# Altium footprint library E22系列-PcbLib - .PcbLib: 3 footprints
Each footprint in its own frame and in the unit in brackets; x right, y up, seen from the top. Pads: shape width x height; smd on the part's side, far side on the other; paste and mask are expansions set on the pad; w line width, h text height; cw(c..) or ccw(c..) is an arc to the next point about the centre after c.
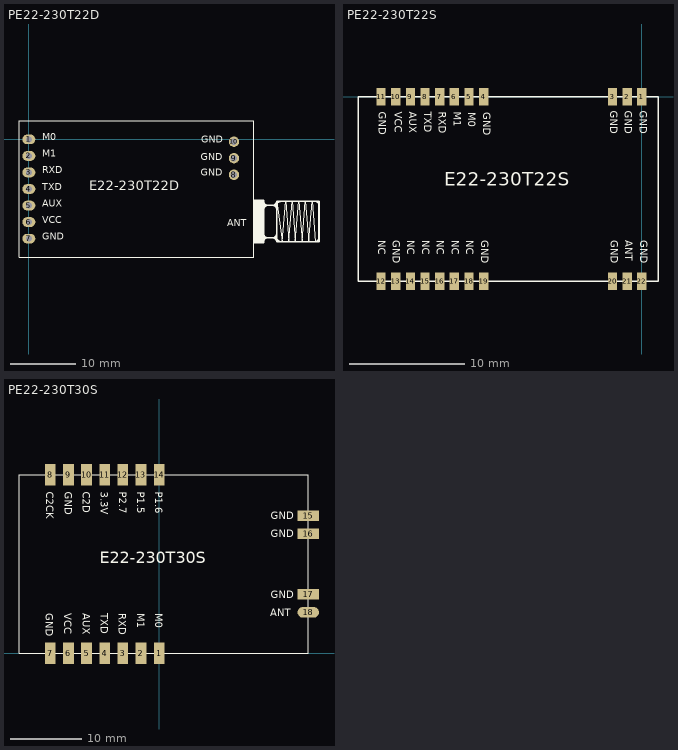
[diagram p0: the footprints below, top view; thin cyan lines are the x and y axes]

## PE22-230T22D [mm] "36mm*21mm-D/SMA长度12.5mm"
pads (10):
  oval 2x1.5 hole 0.9: 1(0,0) 2(0,-2.54) 3(0,-5.08) 4(0,-7.62) 5(0,-10.16) 6(0,-12.7) 7(0,-15.24)
  round 1.6 hole 1: 8(31.49,-5.43) 9(31.49,-2.89) 10(31.49,-0.35)
Top Overlay:
  rectangle: 34.54,-15.865 36.04,-9.365
  rectangle: 34.54,-15.87 36.04,-9.37
  lines w0.1: 38.89,-15.72 38.04,-9.52 38.89,-15.72 ; 38.89,-15.72 39.41,-9.52 ; 38.89,-15.72 39.41,-9.52 ; 39.41,-9.52 39.92,-15.72 ; 39.41,-9.52 39.92,-15.72 ; 39.92,-15.72 40.43,-9.52 ; 39.92,-15.72 40.43,-9.52 ; 40.43,-9.52 40.91,-15.72 ; 40.43,-9.52 40.91,-15.72 ; 40.91,-15.72 41.43,-9.52 ; 40.91,-15.72 41.43,-9.52 ; 41.43,-9.52 41.94,-15.72 ; 41.43,-9.52 41.94,-15.72 ; 41.94,-15.72 42.43,-9.52 ; 41.94,-15.72 42.43,-9.52 ; 42.43,-9.52 42.95,-15.72 ; 42.43,-9.52 42.95,-15.72 ; 42.95,-15.72 43.47,-9.52 ; 42.95,-15.72 43.47,-9.52 ; 43.47,-9.52 43.98,-15.72 43.47,-9.52 ; -1.51,-18.12 -1.51,2.88 34.558,2.88 34.558,-18.12 -1.51,-18.12
  lines w0.254: 34.54,-15.87 34.54,-9.37 ; 34.54,-15.87 36.04,-15.87 ; 34.54,-15.87 34.54,-9.37 ; 34.54,-15.87 36.04,-15.87 ; 34.54,-9.37 36.04,-9.37 ; 34.54,-9.37 36.04,-9.37 ; 36.04,-15.87 36.04,-9.37 ; 36.04,-15.87 36.04,-9.37 ; 36.04,-14.47 ccw(c36.69,-14.47) 36.69,-15.12 ; 36.04,-14.47 ccw(c36.69,-14.47) 36.69,-15.12 ; 36.04,-14.47 36.04,-14.1 36.04,-14.47 ; 36.04,-10.82 cw(c36.74,-10.82) 36.74,-10.12 ; 36.04,-10.82 cw(c36.74,-10.82) 36.74,-10.12 ; 36.04,-10.82 36.04,-11.74 36.04,-10.82 ; 36.04,-9.49 ccw(c36.67,-9.49) 36.67,-10.12 ; 36.04,-9.49 ccw(c36.67,-9.49) 36.67,-10.12 ; 36.04,-9.49 36.04,-9.37 ; 36.04,-9.49 36.04,-9.37 ; 36.59,-15.12 ccw(c36.59,-15.67) 36.04,-15.67 cw(c36.59,-15.67) 36.59,-15.12 ; 36.59,-15.12 37.44,-15.12 ; 36.59,-15.12 37.44,-15.12 ; 36.67,-10.12 37.44,-10.12 ; 36.67,-10.12 37.44,-10.12 ; 36.69,-15.12 37.41,-15.12 ; 36.69,-15.12 37.41,-15.12 ; 36.74,-10.12 37.44,-10.12 ; 36.74,-10.12 37.44,-10.12 ; 37.41,-15.12 ccw(c37.41,-14.49) 38.04,-14.49 cw(c37.41,-14.49) 37.41,-15.12 ; 37.44,-15.12 cw(c37.44,-15.72) 38.04,-15.72 ; 37.44,-15.12 cw(c37.44,-15.72) 38.04,-15.72 ; 37.44,-10.12 ccw(c37.44,-9.52) 38.04,-9.52 ; 37.44,-10.12 cw(c37.44,-10.72) 38.04,-10.72 ccw(c37.44,-10.72) 37.44,-10.12 ; 37.44,-10.12 ccw(c37.44,-9.52) 38.04,-9.52 ; 38.04,-15.72 44.54,-15.72 ; 38.04,-15.72 38.04,-9.52 ; 38.04,-15.72 44.54,-15.72 ; 38.04,-15.72 38.04,-9.52 ; 38.04,-9.52 44.54,-9.52 ; 38.04,-9.52 44.54,-9.52 ; 38.72,-15.72 cw(c38.72,-15.04) 38.04,-15.04 ccw(c38.72,-15.04) 38.72,-15.72 ; 38.72,-15.72 38.87,-15.72 38.72,-15.72 ; 43.92,-15.72 ccw(c43.92,-15.1) 44.54,-15.1 cw(c43.92,-15.1) 43.92,-15.72 ; 43.92,-15.72 43.69,-15.72 43.92,-15.72 ; 44,-9.52 cw(c44,-10.06) 44.54,-10.06 ccw(c44,-10.06) 44,-9.52 ; 44,-9.52 43.6,-9.52 44,-9.52 ; 44.54,-15.72 44.54,-9.52 ; 44.54,-15.72 44.54,-9.52 ; 35.87,-15.12 38.04,-15.12 35.87,-15.12 ; 36.04,-10.12 38.04,-10.12 36.04,-10.12 ; 38.04,-10.13 cw(c38.65,-10.13) 38.65,-9.52 ccw(c38.65,-10.13) 38.04,-10.13
  text "E22-230T22D" at 9.271,-8.382 h2.5
  text "GND" at 26.416,-5.969 h1.8
  text "GND" at 26.416,-3.556 h1.8
  text "GND" at 26.447,-0.921 h1.8
  text "ANT" at 30.48,-13.716 h1.8
  text "M0" at 2.063,-0.54 h1.8
  text "M1" at 2.063,-3.08 h1.8
  text "RXD" at 2.063,-5.62 h1.8
  text "TXD" at 2.063,-8.16 h1.8
  text "AUX" at 2.063,-10.7 h1.8
  text "VCC" at 2.063,-13.24 h1.8
  text "GND" at 2.063,-15.78 h1.8

## PE22-230T22S [mm] "26mm**16mm*3.23mm-S"
pads (22):
  rect 0.8x1.5 smd: 1(0,0) 2(-1.27,0) 3(-2.54,0) 4(-13.71,0) 5(-14.98,0) 6(-16.25,0) 7(-17.52,0) 8(-18.79,0) 9(-20.06,0) 10(-21.33,0) 11(-22.6,0) 12(-22.6,-16) 13(-21.33,-16) 14(-20.06,-16) 15(-18.79,-16) 16(-17.52,-16) 17(-16.25,-16) 18(-14.98,-16) 19(-13.71,-16) 20(-2.54,-16) 21(-1.27,-16) 22(0,-16)
Top Overlay:
  lines w0.127: -24.6,-16 1.4,-16 1.4,0 -24.6,0 -24.6,-16
  text "GND" at -1.687,-1.224 h1.1
  text "GND" at -2.966,-1.224 h1.1
  text "GND" at -2.916,-12.441 h1.1
  text "ANT" at -1.637,-12.441 h1.1
  text "GND" at -0.358,-12.441 h1.1
  text "GND" at -14.138,-12.441 h1.1
  text "NC" at -15.417,-12.441 h1.1
  text "NC" at -16.696,-12.441 h1.1
  text "NC" at -17.974,-12.441 h1.1
  text "NC" at -19.253,-12.441 h1.1
  text "NC" at -20.532,-12.441 h1.1
  text "GND" at -21.811,-12.441 h1.1
  text "NC" at -23.06,-12.441 h1.1
  text "GND" at -13.97,-1.351 h1.1
  text "GND" at -23.01,-1.301 h1.1
  text "VCC" at -21.651,-1.301 h1.1
  text "AUX" at -20.372,-1.301 h1.1
  text "TXD" at -19.093,-1.301 h1.1
  text "RXD" at -17.814,-1.301 h1.1
  text "M1" at -16.536,-1.301 h1.1
  text "M0" at -15.257,-1.351 h1.1
  text "E22-230T22S" at -17.107,-8.126 h2
  text "GND" at -0.408,-1.224 h1.1

## PE22-230T30S [mm] "40.5mm*25mm*3.80mm-S"
pads (18):
  rect 1.5x3 smd: 1(0,0) 2(-2.54,0) 3(-5.08,0) 4(-7.62,0) 5(-10.16,0) 6(-12.7,0) 7(-15.24,0) 8(-15.24,25) 9(-12.7,25) 10(-10.16,25) 11(-7.62,25) 12(-5.08,25) 13(-2.54,25) 14(0,25)
  rect 3x1.5 smd: 15(20.88,19.27) 16(20.88,16.73) 17(20.88,8.27)
  oval 3x1.5 smd: 18(20.88,5.73)
Top Overlay:
  lines w0.127: -19.62,0 -19.62,25 20.88,25 20.88,0 -19.62,0
  text "E22-230T30S" at -8.317,12.065 h2.8
  text "GND" at 15.602,7.72 h1
  text "ANT" at 15.554,5.17 h1
  text "M0" at -0.577,5.575 h1
  text "M1" at -3.087,5.575 h1
  text "RXD" at -5.637,5.575 h1
  text "TXD" at -8.167,5.575 h1
  text "AUX" at -10.707,5.575 h1
  text "VCC" at -13.257,5.575 h1
  text "GND" at -15.847,5.575 h1
  text "C2CK" at -15.827,22.592 h1
  text "GND" at -13.237,22.592 h1
  text "3.3V" at -8.147,22.592 h1
  text "P2.7" at -5.617,22.592 h1
  text "P1.5" at -3.067,22.592 h1
  text "P1.6" at -0.557,22.592 h1
  text "GND" at 15.602,16.22 h1
  text "GND" at 15.602,18.73 h1
  text "C2D" at -10.73,22.606 h1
